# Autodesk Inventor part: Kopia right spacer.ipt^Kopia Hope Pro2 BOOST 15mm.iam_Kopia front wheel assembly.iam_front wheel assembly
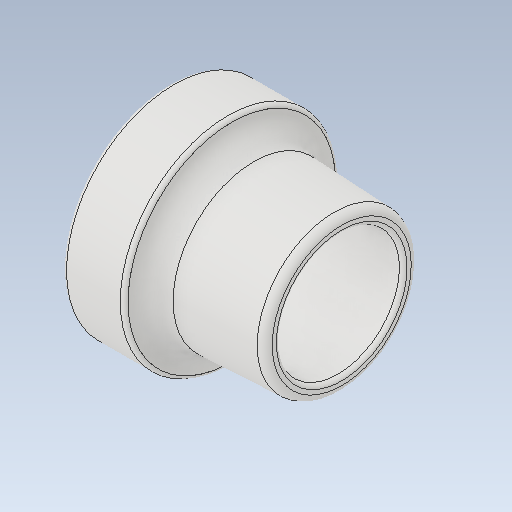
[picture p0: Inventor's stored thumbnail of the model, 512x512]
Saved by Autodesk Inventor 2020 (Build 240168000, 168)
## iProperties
Created: 2017-09
Part Number: Kopia right spacer.ipt^Kopia Hope Pro2 BOOST 15mm.iam_Kopia front wheel assembly.iam_front wheel assembly
Material: Ogólny
Document SubType Name: Modeling
Designer: Tomasz
Density: 1 g/cm^3
Appearance: Domyślna
Sending System: SolidWorks 2017
Last Author: Tomasz
Last Saved: 2017-09-11
Author: Tomasz
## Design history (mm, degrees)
feature "right spacer.ipt"
node "Bryła1"
